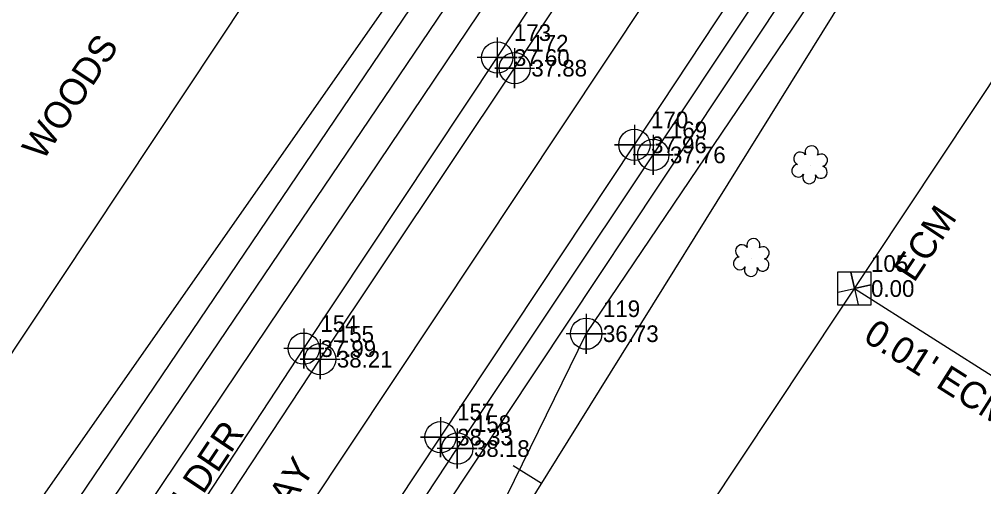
# Model space of a CAD drawing. Extents: x 2603627 to 2605187, y 896619 to 899063.
# Drawn here: x 2604072.2 to 2604216.9, y 897519.1 to 897589.3 of the extents above; entities that cross this region are included whole.
import ezdxf

# ---------------------------------------------------------------- set-up
doc = ezdxf.new("R2010")
doc.units = 0
for name, color, linetype in [('Exist Horizontal Alignment', 7, 'Continuous'), ('Exist Horizontal Baseline Alignment', 7, 'Continuous'), ('Exist Horizontal Baseline Alignment Tick small', 7, 'Continuous'), ('Exist Property Corner CELL', 7, 'Continuous'), ('Exist Property Line', 7, 'Continuous'), ('Exist Property Line Text', 7, 'Continuous'), ('Exist Property Monument CELL', 7, 'Continuous'), ('Exist Property Monument Cogo Elevation', 7, 'Continuous'), ('Exist Property Monument Cogo Number', 7, 'Continuous'), ('Exist Property Monument Text', 7, 'Continuous'), ('Exist Right of Way Line', 7, 'Continuous'), ('Exist Roads EOP', 7, 'Continuous'), ('Exist Roads EOP Cogo Elevation', 7, 'Continuous'), ('Exist Roads EOP Cogo Number', 7, 'Continuous'), ('Exist Roads EOP Cogo Point CELL', 7, 'Continuous'), ('Exist Roads EOP Text', 7, 'Continuous'), ('Exist Roads EOT', 7, 'Continuous'), ('Exist Roads EOT Cogo Elevation', 7, 'Continuous'), ('Exist Roads EOT Cogo Number', 7, 'Continuous'), ('Exist Roads EOT Cogo Point CELL', 7, 'Continuous'), ('Exist Roads EOT Text', 7, 'Continuous'), ('Exist Utilities Telephone UG Cable SUE LOS C', 7, 'Continuous'), ('Exist Utilities Telephone UG FO SUE LOS C', 7, 'Continuous'), ('Exist Utilities Water UG Line SUE LOS B', 7, 'Continuous'), ('Exist Utilities Water UG Line SUE LOS B Cogo Elevation', 7, 'Continuous'), ('Exist Utilities Water UG Line SUE LOS B Cogo Number', 7, 'Continuous'), ('Exist Utilities Water UG Line SUE LOS B Cogo Point CELL', 7, 'Continuous'), ('Exist Vegetation Shrub CELL', 7, 'Continuous'), ('Exist Vegetation Woods Line', 7, 'Continuous'), ('Exist Vegetation Woods Line Text', 7, 'Continuous')]:
    doc.layers.add(name, color=color, linetype=linetype)

# ---------------------------------------------------------------- blocks, each defined once
blk = doc.blocks.new('EXIST UTILITIES WATER UG LINE SUE LOS B COGO POINT')
at = {"layer": 'Exist Utilities Water UG Line SUE LOS B Cogo Point CELL'}
blk.add_lwpolyline([(0, 0.06), (0, -0.06), (0, 0), (0.06, 0), (-0.06, 0)], dxfattribs=at)
blk.add_circle((0, 0), 0.0469, dxfattribs=at)
blk = doc.blocks.new('EXIST ROADS EOP COGO POINT')
at = {"layer": 'Exist Roads EOP Cogo Point CELL'}
blk.add_lwpolyline([(0, 0.06), (0, -0.06), (0, 0), (0.06, 0), (-0.06, 0)], dxfattribs=at)
blk.add_circle((0, 0), 0.0469, dxfattribs=at)
blk = doc.blocks.new('EXIST ROADS EOT COGO POINT')
at = {"layer": 'Exist Roads EOT Cogo Point CELL'}
blk.add_lwpolyline([(0, 0.06), (0, -0.06), (0, 0), (-0.06, 0), (0.06, 0)], dxfattribs=at)
blk.add_circle((0, 0), 0.0469, dxfattribs=at)
blk = doc.blocks.new('EXIST PROPERTY MONUMENT')
at = {"layer": 'Exist Property Monument CELL'}
blk.add_line((0, 0), (0, 0), dxfattribs=at)
blk.add_lwpolyline([(-0.0499, -0.0499), (-0.0499, 0.0499), (0.0499, 0.0499), (0.0499, -0.0499), (-0.0499, -0.0499)], dxfattribs=at)

msp = doc.modelspace()

# ---------------------------------------------------------------- linework, layer by layer
at = {"layer": 'Exist Horizontal Alignment'}
msp.add_line((2604046.33, 897411.6), (2604501.12, 898096.36), dxfattribs=at)
at = {"layer": 'Exist Horizontal Baseline Alignment'}
msp.add_line((2604070.2, 897390.44), (2604301.74, 897762.53), dxfattribs=at)
at = {"layer": 'Exist Horizontal Baseline Alignment Tick small'}
msp.add_line((2604150.59, 897519.62), (2604146.34, 897522.27), dxfattribs=at)
at = {"layer": 'Exist Property Corner CELL'}
msp.add_line((2604197.54, 897548.89), (2604197.54, 897548.89), dxfattribs=at)
msp.add_lwpolyline([(2604195.1, 897548.34), (2604199.98, 897549.43), (2604197.54, 897548.89), (2604196.99, 897551.33), (2604198.08, 897546.45)], dxfattribs=at)
at = {"layer": 'Exist Property Line'}
msp.add_line((2604197.54, 897548.89), (2604392.99, 897424.83), dxfattribs=at)
at = {"layer": 'Exist Right of Way Line'}
for p, q in [((2604004.68, 897439.26), (2604459.47, 898124.02)), ((2604087.98, 897383.94), (2604542.77, 898068.69))]:
    msp.add_line(p, q, dxfattribs=at)
at = {"layer": 'Exist Roads EOP'}
for points in [[(2604034.94, 897419.16), (2604054.97, 897449.51), (2604085.58, 897495.18), (2604114.88, 897539.87), (2604143.93, 897583.57), (2604172.72, 897627.19), (2604201.64, 897670.62), (2604230.5, 897714.45), (2604261.1, 897760.21), (2604291.23, 897805.76), (2604320.82, 897850.24), (2604350.34, 897894.81), (2604379.01, 897938.02), (2604408.4, 897982.56), (2604438.29, 898027.28), (2604468.22, 898072.28), (2604496.92, 898115.7)], [(2604057.72, 897404.05), (2604078.22, 897434.83), (2604108.36, 897480.05), (2604137.93, 897524.86), (2604167.35, 897568.96), (2604196.06, 897612.17), (2604224.86, 897655.68), (2604253.51, 897698.95), (2604283.96, 897744.64), (2604314.74, 897791.03), (2604343.97, 897835.34), (2604373.31, 897879.6), (2604402.1, 897923.18), (2604431.64, 897967.59), (2604461.24, 898012.02), (2604491.05, 898056.88), (2604519.7, 898100.47)]]:
    msp.add_lwpolyline(points, dxfattribs=at)
at = {"layer": 'Exist Roads EOT'}
for points in [[(2604037.37, 897417.54), (2604057.46, 897447.93), (2604087.91, 897493.66), (2604117.35, 897538.28), (2604146.54, 897581.98), (2604175.28, 897625.51), (2604204.1, 897668.97), (2604233.05, 897712.63), (2604263.81, 897758.51), (2604293.89, 897804.07), (2604323.3, 897848.54), (2604352.86, 897893.08), (2604381.65, 897936.11), (2604411.04, 897980.65), (2604440.78, 898025.82), (2604470.61, 898070.74), (2604499.36, 898114.11)], [(2604055.13, 897405.77), (2604075.39, 897436.3), (2604105.72, 897481.84), (2604135.41, 897526.58), (2604164.51, 897570.47), (2604193.14, 897613.84), (2604222.02, 897657.58), (2604250.73, 897700.63), (2604281.08, 897746.07), (2604311.9, 897792.56), (2604341.37, 897836.94), (2604370.82, 897881.24), (2604399.64, 897924.71), (2604429.03, 897968.88), (2604458.85, 898013.95), (2604488.44, 898058.33), (2604517.14, 898101.52)]]:
    msp.add_lwpolyline(points, dxfattribs=at)
at = {"layer": 'Exist Utilities Telephone UG Cable SUE LOS C'}
for p, q in [((2604109.59, 897543.22), (2604364.02, 897921.59)), ((2604060.46, 897402.24), (2604201.56, 897614.6)), ((2604028.87, 897423.18), (2604109.59, 897543.22))]:
    msp.add_line(p, q, dxfattribs=at)
at = {"layer": 'Exist Utilities Telephone UG FO SUE LOS C'}
for p, q in [((2604020.98, 897428.41), (2604461.82, 898080.46)), ((2604024.53, 897426.06), (2604465.37, 898078.1))]:
    msp.add_line(p, q, dxfattribs=at)
at = {"layer": 'Exist Utilities Water UG Line SUE LOS B'}
msp.add_lwpolyline([(2604076.5, 897391.6), (2604089.19, 897412.44), (2604108.02, 897444.81), (2604130.46, 897486.17), (2604138.61, 897502.5), (2604141.74, 897510.42), (2604157.29, 897542.11), (2604195.61, 897598.86), (2604232.99, 897655.2), (2604269.72, 897709.19), (2604303.43, 897758.71), (2604343.24, 897819.02), (2604371.6, 897861.28), (2604402.52, 897906.63), (2604434.42, 897955.25), (2604460.63, 897996.69), (2604477.79, 898022.59), (2604502.25, 898059.64), (2604529.4, 898098.89), (2604530.47, 898100.43), (2604537.02, 898109.88), (2604550.55, 898129.28)], dxfattribs=at)
at = {"layer": 'Exist Vegetation Shrub CELL'}
for p, q in [((2604190.89, 897567.3), (2604190.89, 897567.3)), ((2604182.14, 897553.37), (2604182.14, 897553.37))]:
    msp.add_line(p, q, dxfattribs=at)
for centre, radius, start, end in [((2604189.4, 897568.42), 0.968, 35.8908, 245.4216), ((2604191.11, 897569.34), 0.99, 334.8391, 200.4717), ((2604192.56, 897568.16), 0.929, 284.4567, 126.0861), ((2604189.09, 897566.59), 0.955, 95.1099, 327.9534), ((2604192.52, 897566.37), 0.937, 204.9913, 73.4601), ((2604190.76, 897565.61), 0.984, 151.2797, 21.387), ((2604182.37, 897555.41), 0.99, 334.8391, 200.4717), ((2604180.66, 897554.5), 0.968, 35.8908, 245.4216), ((2604183.81, 897554.24), 0.929, 284.4567, 126.0861), ((2604180.34, 897552.67), 0.955, 95.1099, 327.9534), ((2604183.78, 897552.44), 0.937, 204.9913, 73.4601), ((2604182.01, 897551.69), 0.984, 151.2797, 21.387)]:
    msp.add_arc(centre, radius, start, end, dxfattribs=at)
at = {"layer": 'Exist Vegetation Woods Line'}
msp.add_lwpolyline([(2604185.5, 897674.67), (2604015.65, 897431.94)], dxfattribs=at)

# ---------------------------------------------------------------- block references
at = {"layer": 'Exist Property Monument CELL', "xscale": 50, "yscale": 50}
msp.add_blockref('EXIST PROPERTY MONUMENT', (2604197.53, 897548.89), dxfattribs=at)
at = {"layer": 'Exist Roads EOP Cogo Point CELL', "xscale": 50, "yscale": 50}
for p in [(2604143.93, 897583.57), (2604167.35, 897568.96), (2604114.88, 897539.87), (2604137.93, 897524.86)]:
    msp.add_blockref('EXIST ROADS EOP COGO POINT', p, dxfattribs=at)
at = {"layer": 'Exist Roads EOT Cogo Point CELL', "xscale": 50, "yscale": 50}
for p in [(2604146.54, 897581.98), (2604164.51, 897570.47), (2604117.35, 897538.28), (2604135.41, 897526.58)]:
    msp.add_blockref('EXIST ROADS EOT COGO POINT', p, dxfattribs=at)
at = {"layer": 'Exist Utilities Water UG Line SUE LOS B Cogo Point CELL', "xscale": 50, "yscale": 50}
msp.add_blockref('EXIST UTILITIES WATER UG LINE SUE LOS B COGO POINT', (2604157.29, 897542.11), dxfattribs=at)

# ---------------------------------------------------------------- texts
at = {"layer": 'Exist Property Line Text'}
msp.add_text("0.01' ECM TO R/W", height=4, rotation=327.5958, dxfattribs=at).set_placement((2604198.67, 897541.14))
at = {"layer": 'Exist Property Monument Cogo Elevation'}
msp.add_text('0.00', height=2.5, dxfattribs=at).set_placement((2604200.03, 897547.64))
at = {"layer": 'Exist Property Monument Cogo Number'}
msp.add_text('105', height=2.5, dxfattribs=at).set_placement((2604200.03, 897551.39))
at = {"layer": 'Exist Property Monument Text'}
msp.add_text('ECM', height=4, rotation=56.4785, dxfattribs=at).set_placement((2604206.49, 897549.66))
at = {"layer": 'Exist Roads EOP Cogo Elevation'}
for s, p in [('37.60', (2604146.43, 897582.32)), ('37.76', (2604169.85, 897567.71)), ('37.99', (2604117.38, 897538.62)), ('38.18', (2604140.43, 897523.61))]:
    msp.add_text(s, height=2.5, dxfattribs=at).set_placement(p)
at = {"layer": 'Exist Roads EOP Cogo Number'}
for s, p in [('173', (2604146.43, 897586.07)), ('169', (2604169.85, 897571.46)), ('154', (2604117.38, 897542.37)), ('158', (2604140.43, 897527.36))]:
    msp.add_text(s, height=2.5, dxfattribs=at).set_placement(p)
at = {"layer": 'Exist Roads EOP Text'}
msp.add_text("3' PAVED SHOULDER", height=4, rotation=56.1634, dxfattribs=at).set_placement((2604075.55, 897481.7))
at = {"layer": 'Exist Roads EOT Cogo Elevation'}
for s, p in [('37.88', (2604149.04, 897580.73)), ('37.96', (2604167.01, 897569.22)), ('38.21', (2604119.85, 897537.03)), ('38.33', (2604137.91, 897525.33))]:
    msp.add_text(s, height=2.5, dxfattribs=at).set_placement(p)
at = {"layer": 'Exist Roads EOT Cogo Number'}
for s, p in [('172', (2604149.04, 897584.48)), ('170', (2604167.01, 897572.97)), ('155', (2604119.85, 897540.78)), ('157', (2604137.91, 897529.08))]:
    msp.add_text(s, height=2.5, dxfattribs=at).set_placement(p)
at = {"layer": 'Exist Roads EOT Text'}
msp.add_text(" US 13 21' PAVED ROADWAY", height=4, rotation=56.3361, dxfattribs=at).set_placement((2604075.88, 897460.53))
at = {"layer": 'Exist Utilities Water UG Line SUE LOS B Cogo Elevation'}
msp.add_text('36.73', height=2.5, dxfattribs=at).set_placement((2604159.79, 897540.86))
at = {"layer": 'Exist Utilities Water UG Line SUE LOS B Cogo Number'}
msp.add_text('119', height=2.5, dxfattribs=at).set_placement((2604159.79, 897544.61))
at = {"layer": 'Exist Vegetation Woods Line Text'}
msp.add_text('WOODS', height=4, rotation=56.4094, dxfattribs=at).set_placement((2604075.72, 897567.94))

doc.saveas('drawing.dxf')
